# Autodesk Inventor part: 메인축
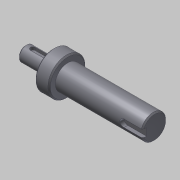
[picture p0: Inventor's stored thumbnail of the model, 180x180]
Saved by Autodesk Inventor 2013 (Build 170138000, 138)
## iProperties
Created: 2018-09
Part Number: 메인축
Document SubType Name: Modeling
Density: 7.86 g/cm^3
Material: 강철, 연강
Mass: 251.949 g
Surface Area: 77.4403 cm^2
Volume: 32.0546 cm^3
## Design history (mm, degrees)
sketch "스케치1"
  geometry: L1 (34.997, -37.5)-(34.997, -77.5) reference; L2 (46.5, -38.401)-(46.5, -76.599) reference; L3 (12.497, -57.5)-(116.5, -57.5); L4 (12.497, -63.5)-(34.997, -63.5); L5 (34.997, -72.5)-(46.5, -72.5); L6 (46.5, -67.5)-(116.5, -67.5); L7 (116.5, -67.5)-(116.5, -57.5); L8 (12.497, -63.5)-(12.497, -57.5); 2 further points
  constraints: 12 end point, 5 point on line, 4 perpendicular, 1 midpoint, 1 parallel
  dimensions: "d0" = 20 diameter of L6 L3; "d1" = 30 diameter of L5 L3; "d2" = 22.5 distance of L4.start L4.end; "d3" = 70 distance of L6.start L6.end; "d5" = 12 diameter of L4 L3
revolve "회전1" sketch "스케치1" stored, may be unused: angle "d4" = 90 deg
chamfer "모따기1" distance "d6" = 1; stored, may be unused: second distance "d7" = 2, angle "d8" = 45 deg
node "작업 평면1"
sketch "스케치2"
  geometry: L1 (-11.25, -5)-(-11.25, 5) reference; L2 (-5.25, 2)-(4.75, 2); L3 (4.75, -2)-(-5.25, -2); A1 r 2 centre (4.75, 0) between (4.75, -2) and (4.75, 2); A2 r 2 centre (-5.25, 0) between (-5.25, 2) and (-5.25, -2); 2 further points
  constraints: 4 end point, 4 point on circle, 4 tangent, 2 centre point, 1 horizontal alignment, 1 midpoint, 1 parallel, 1 perpendicular
  dimensions: "d9" = 4 distance between parallel lines of L3 L2; "d10" = 14 dimension on A1 A2; "d11" = 4 distance edge to line of A2 L1
extrude "돌출1" cut sketch "스케치2" distance "d12" = 2.5; taper "d13" = 0 deg
node "작업 평면2"
sketch "스케치3"
  geometry: L1 (35, 9)-(35, -9) reference; L2 (35, 3)-(20, 3); L3 (20, -3)-(35, -3); A1 r 3 centre (20, 0) between (20, 3) and (20, -3); 2 further points
  constraints: 4 end point, 2 perpendicular, 2 point on circle, 2 point on line, 2 tangent, 1 centre point, 1 horizontal alignment, 1 midpoint
  dimensions: "d14" = 6 distance between parallel lines of L3 L2; "d15" = 18 dimension on A1 L1
extrude "돌출2" cut sketch "스케치3" distance "d16" = 3.5; taper "d17" = 0 deg
node "솔리드1"
node "참조1"
node "참조2"
